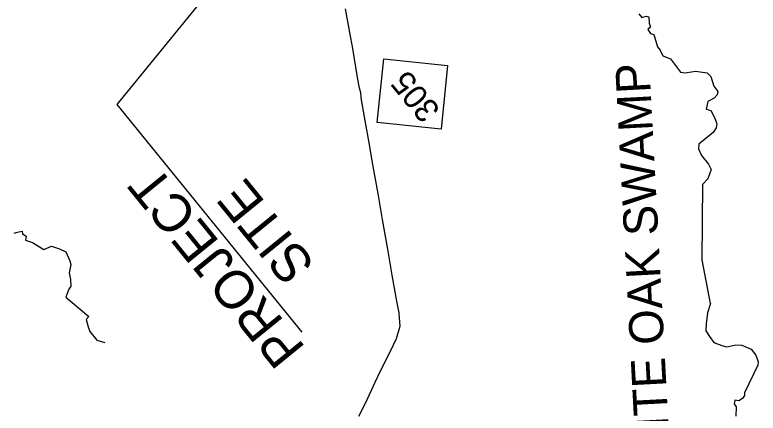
# Model space of a CAD drawing. Extents: x 2596159 to 2598075, y 851667 to 853493.
# Drawn here: x 2597143.5 to 2597274.4, y 851821.9 to 851892 of the extents above; entities that cross this region are included whole.
import ezdxf

# ---------------------------------------------------------------- set-up
doc = ezdxf.new("R2010")
doc.units = 0
doc.layers.add('Old_Level_1', color=7, linetype='Continuous')

msp = doc.modelspace()

# ---------------------------------------------------------------- linework, layer by layer
at = {"layer": 'Old_Level_1'}
for p, q in [((2597197.71, 851920.8), (2597161.42, 851876.24)), ((2597201.62, 851893.13), (2597202.39, 851888.93)), ((2597253.39, 851892.24), (2597253.91, 851891.6)), ((2597253.91, 851891.6), (2597254.64, 851891.84)), ((2597254.64, 851891.84), (2597255.13, 851891.72)), ((2597255.13, 851891.72), (2597255.18, 851890.59)), ((2597255.18, 851890.59), (2597255.45, 851889.88)), ((2597255.45, 851889.88), (2597254.94, 851889.47)), ((2597254.94, 851889.47), (2597255.43, 851888.76)), ((2597202.39, 851888.93), (2597202.91, 851886.11)), ((2597255.43, 851888.76), (2597256, 851888.6)), ((2597256, 851888.6), (2597256.69, 851886.42)), ((2597256.69, 851886.42), (2597257.14, 851885.81)), ((2597202.91, 851886.11), (2597203.72, 851881.38)), ((2597257.14, 851885.81), (2597257.61, 851884.83)), ((2597257.61, 851884.83), (2597258.96, 851884.31)), ((2597258.96, 851884.31), (2597260.72, 851881.96)), ((2597203.72, 851881.38), (2597204.07, 851879.4)), ((2597260.72, 851881.96), (2597261.55, 851881.86)), ((2597261.55, 851881.86), (2597263.37, 851882.14)), ((2597263.37, 851882.14), (2597265.42, 851881.83)), ((2597265.42, 851881.83), (2597266.05, 851881.19)), ((2597266.05, 851881.19), (2597266.57, 851879.51)), ((2597204.07, 851879.4), (2597204.33, 851878.35)), ((2597266.57, 851879.51), (2597267.31, 851878.56)), ((2597267.31, 851878.56), (2597267.19, 851877.93)), ((2597204.33, 851878.35), (2597204.42, 851877.41)), ((2597204.42, 851877.41), (2597205, 851874.08)), ((2597266.65, 851877.4), (2597265.55, 851876.77)), ((2597267.19, 851877.93), (2597266.65, 851877.4)), ((2597161.42, 851876.24), (2597194.01, 851836.14)), ((2597265.55, 851876.77), (2597265.25, 851875.42)), ((2597265.25, 851875.42), (2597266.03, 851875.17)), ((2597266.03, 851875.17), (2597266.77, 851873.82)), ((2597205, 851874.08), (2597205.83, 851869.53)), ((2597266.77, 851873.82), (2597267.14, 851872.85)), ((2597267, 851872.15), (2597266.47, 851871.32)), ((2597267.14, 851872.85), (2597267, 851872.15)), ((2597266.47, 851871.32), (2597263.96, 851869.27)), ((2597205.83, 851869.53), (2597206.45, 851865.69)), ((2597263.96, 851869.27), (2597263.89, 851868.44)), ((2597263.89, 851868.44), (2597264.43, 851867.28)), ((2597264.43, 851867.28), (2597265.65, 851865.77)), ((2597206.45, 851865.69), (2597207.44, 851860.22)), ((2597265.65, 851865.77), (2597266.13, 851864.8)), ((2597266.13, 851864.8), (2597265.55, 851863.15)), ((2597265.55, 851863.15), (2597264.67, 851862.25)), ((2597264.51, 851848.9), (2597264.67, 851862.25)), ((2597207.44, 851860.22), (2597208.18, 851856.01)), ((2597208.18, 851856.01), (2597209.09, 851850.77)), ((2597143.36, 851853.6), (2597143.71, 851853.71)), ((2597143.71, 851853.71), (2597144.15, 851853.85)), ((2597144.15, 851853.85), (2597144.74, 851853.94)), ((2597144.74, 851853.94), (2597144.81, 851853.45)), ((2597144.81, 851853.45), (2597145.44, 851853.08)), ((2597145.44, 851853.08), (2597145.31, 851852.36)), ((2597145.31, 851852.36), (2597146.55, 851851.92)), ((2597146.55, 851851.92), (2597148.58, 851850.71)), ((2597148.58, 851850.71), (2597149.92, 851851.3)), ((2597149.92, 851851.3), (2597151.3, 851850.82)), ((2597151.3, 851850.82), (2597152.44, 851850.31)), ((2597152.44, 851850.31), (2597153.16, 851848.74)), ((2597209.09, 851850.77), (2597209.89, 851846.22)), ((2597153.16, 851848.74), (2597153.33, 851848.05)), ((2597265.99, 851841.22), (2597264.51, 851848.9)), ((2597153.33, 851848.05), (2597153, 851846.63)), ((2597153, 851846.63), (2597153.27, 851845.41)), ((2597209.89, 851846.22), (2597210.69, 851841.6)), ((2597153.27, 851845.41), (2597153.31, 851844.28)), ((2597152.98, 851843.73), (2597152.44, 851842.3)), ((2597153.31, 851844.28), (2597152.98, 851843.73)), ((2597152.44, 851842.3), (2597156.47, 851838.89)), ((2597210.69, 851841.6), (2597211.07, 851839.55)), ((2597265.99, 851841.22), (2597265.46, 851839.57)), ((2597211.07, 851839.55), (2597211.18, 851838.6)), ((2597265.46, 851839.57), (2597265.24, 851837.63)), ((2597156.47, 851838.89), (2597156.02, 851838.36)), ((2597156.02, 851838.36), (2597156.34, 851837.12)), ((2597211.18, 851838.6), (2597211.25, 851837.28)), ((2597156.34, 851837.12), (2597156.67, 851836.25)), ((2597211.14, 851836.77), (2597210.71, 851835.19)), ((2597211.25, 851837.28), (2597211.14, 851836.77)), ((2597265.24, 851837.63), (2597265.17, 851836.37)), ((2597156.67, 851836.25), (2597157.92, 851834.74)), ((2597265.17, 851836.37), (2597265.8, 851835.37)), ((2597265.8, 851835.37), (2597266.58, 851834.34)), ((2597157.92, 851834.74), (2597159.28, 851834.31)), ((2597210.64, 851834.99), (2597209.54, 851832.74)), ((2597210.71, 851835.19), (2597210.64, 851834.99)), ((2597266.58, 851834.34), (2597268, 851833.78)), ((2597268.9, 851833.6), (2597270.48, 851833.94)), ((2597270.48, 851833.94), (2597271.51, 851833.89)), ((2597209.54, 851832.74), (2597207.89, 851829.38)), ((2597268, 851833.78), (2597268.9, 851833.6)), ((2597271.51, 851833.89), (2597273.19, 851833.15)), ((2597273.19, 851833.15), (2597273.98, 851832.13)), ((2597273.98, 851832.13), (2597274.39, 851830.94)), ((2597274.34, 851830.37), (2597272.01, 851825.47)), ((2597274.39, 851830.94), (2597274.34, 851830.37)), ((2597207.89, 851829.38), (2597206.88, 851827.27)), ((2597206.88, 851827.27), (2597205.2, 851823.73)), ((2597271.97, 851824.98), (2597271.65, 851824.49)), ((2597272.01, 851825.47), (2597271.97, 851824.98)), ((2597205.2, 851823.73), (2597203.98, 851821.31)), ((2597270.26, 851824.16), (2597270.19, 851823.55)), ((2597270.19, 851823.55), (2597270.51, 851823.03)), ((2597270.99, 851824.05), (2597270.26, 851824.16)), ((2597271.65, 851824.49), (2597270.99, 851824.05)), ((2597270.51, 851823.03), (2597270.49, 851821.36))]:
    msp.add_line(p, q, dxfattribs=at)
msp.add_lwpolyline([(2597218.53, 851871.93), (2597207.3, 851873.09), (2597208.46, 851884.31), (2597219.69, 851883.15)], close=True, dxfattribs=at)

# ---------------------------------------------------------------- texts
for s, height, rotation, p in [('WHITE OAK SWAMP', 6.0253, 93.0451, (2597259.34, 851805.93)), ('305', 4.193, 129.1029, (2597218.55, 851875.31)), ('PROJECT', 6.724, 129.1028, (2597194.8, 851833.39)), ('SITE', 6.724, 129.1028, (2597196.55, 851848.11))]:
    msp.add_text(s, height=height, rotation=rotation, dxfattribs=at).set_placement(p)

doc.saveas('drawing.dxf')
